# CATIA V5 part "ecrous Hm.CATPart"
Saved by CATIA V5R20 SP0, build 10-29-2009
Part number: Ecrous Hm - M20
Material "X2CrNi18-09": density 7900 kg/m3, Young's modulus 0.2 Pa, Poisson ratio 0.19
Bounding box of the stored display mesh (mm): x -15 to 15, y -17.321 to 17.321, z -5 to 5
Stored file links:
  C:\travail\CAO\bib catia\ecrous\ecrous Hm.CATPart
  C:\travail\CAO\visserie\ecrous H\ecrou H.xls
  C:\travail\CAO\bib catia\ecrous\ecrou Hm.xls
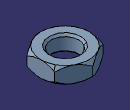
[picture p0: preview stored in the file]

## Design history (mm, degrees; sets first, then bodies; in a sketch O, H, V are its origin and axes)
Parameters
  Designation = "Ecrous Hm - M20" {design table}
  m = 10 mm {design table}
  s = 30 mm {design table}
  p = 2.5 mm {design table}
  d = "M20" {design table}
Body1 (main body)
  Sketch1 on xy-plane, origin (0, 0, 0), H (1, 0, 0), V (0, 1, 0)
    point P1 (15, -8.6603)
    point P2 (15, 8.6603)
    point P3 (0, 17.3205)
    point P4 (-15, 8.6603)
    point P5 (-15, -8.6603)
    point P6 (0, -17.3205)
    point P7 (15, 0)
    construction line L1 (15, -8.6603) -> (15, 8.6603)
    construction line L2 (15, 8.6603) -> (0, 17.3205)
    construction line L3 (0, 17.3205) -> (-15, 8.6603)
    construction line L4 (-15, 8.6603) -> (-15, -8.6603)
    construction line L5 (-15, -8.6603) -> (0, -17.3205)
    construction line L6 (0, -17.3205) -> (15, -8.6603)
    construction line L7 (0, 0) -> (15, 0)
    circle A1 centre (0, 0) radius 17.3205
    construction arc A2 centre (-15, -8.6603) radius 17.3205 from (-15, 8.6603) to (0, -17.3205) cw
    construction arc A3 centre (15, 8.6603) radius 17.3205 from (0, 17.3205) to (15, -8.6603) ccw
    distance L4 L1 = 30 {= s}
    horizontal: L7 H
    coincidence: A1 P1, A1 P2, A1 P3, A1 P4, A1 P5, A1 P6, A2 O, A3 O
    midpoint: P7 L1
  Pad1: profile Sketch1, direction (0, 0, 1), length 5 {= m /2}, mirrored extent
  Sketch2 on end face of Pad1, origin (0, 0, 5), H (1, 0, 0), V (0, 1, 0)
    point P1 (15, -8.6603)
    point P2 (15, 8.6603)
    point P3 (0, 17.3205)
    point P4 (-15, 8.6603)
    point P5 (-15, -8.6603)
    point P6 (0, -17.3205)
    point P7 (15, 0)
    line L1 (15, -8.6603) -> (15, 8.6603)
    line L2 (15, 8.6603) -> (0, 17.3205)
    line L3 (0, 17.3205) -> (-15, 8.6603)
    line L4 (-15, 8.6603) -> (-15, -8.6603)
    line L5 (-15, -8.6603) -> (0, -17.3205)
    line L6 (0, -17.3205) -> (15, -8.6603)
    construction line L7 (0, 0) -> (15, 0)
    construction circle A1 centre (0, 0) radius 17.3205
    construction arc A2 centre (-15, -8.6603) radius 17.3205 from (-15, 8.6603) to (0, -17.3205) cw
    construction arc A3 centre (15, 8.6603) radius 17.3205 from (0, 17.3205) to (15, -8.6603) ccw
    reference projected circle E1 centre (0, 0) radius 17.3205 from edge [face of Pad1 from Sketch1.A1 | end face of Pad1]
    horizontal: L7 H
    coincidence: A1 P1, A1 P2, A1 P3, A1 P4, A1 P5, A1 P6, A2 O, A3 O, P2 E1
    midpoint: P7 L1
    parallelism: L1 L4
  Sketch3 on zx-plane, origin (0, 0, 0), H (-1, 0, 0), V (0, 0, 1)
    point P1 (-17.3205, 5)
    line L1 (-17.3205, 5) -> (-17.3205, 2.6795)
    line L2 (-17.3205, 2.6795) -> (-15, 5)
    point P3 (-15, 5)
    line L3 (-15, 5) -> (-17.3205, 5)
    reference intersected line E1 (-9.2376, 5) -> (9.2376, 5) from end face of Pad1
    point P4 (-17.3205, 5)
    reference projected point E3 (-15, 5) from Sketch2.L1
    axis line L4 (0, 0) -> (0, 13.8114)
    angle L2 L1 = 45
    vertical: L1 V, L4 V
    horizontal: L3 H
    coincidence: L3 E1, P1 P4, P3 E3
  Groove1: profile Sketch3, axis Sketch3.L4, angle 360
  Mirror1: of Groove1, about xy-plane
  Pocket1: profile Sketch2, direction (0, 0, -1), through (limit type 3), outer side
  Sketch4 on end face of Pad1, origin (0, 0, 5), H (1, 0, 0), V (0, 1, 0)
    point P1 (0, 0)
  Hole1: placed by Sketch4, at (0, 0, 5) direction (0, 0, -1), diameter 17.294, through (limit type 6), threaded "M20", thread diameter 20, thread depth 10, pitch 2.5
  Chamfer1: length 1.25 {= p /2}, angle 45, on edge [end face of Pad1 | face of Hole1]; edge [face of Hole1 | start face of Pad1]
Relations
  Hole1.ThreadDescription = d
  design table, configuration 7, drives d, m, s, p, Designation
